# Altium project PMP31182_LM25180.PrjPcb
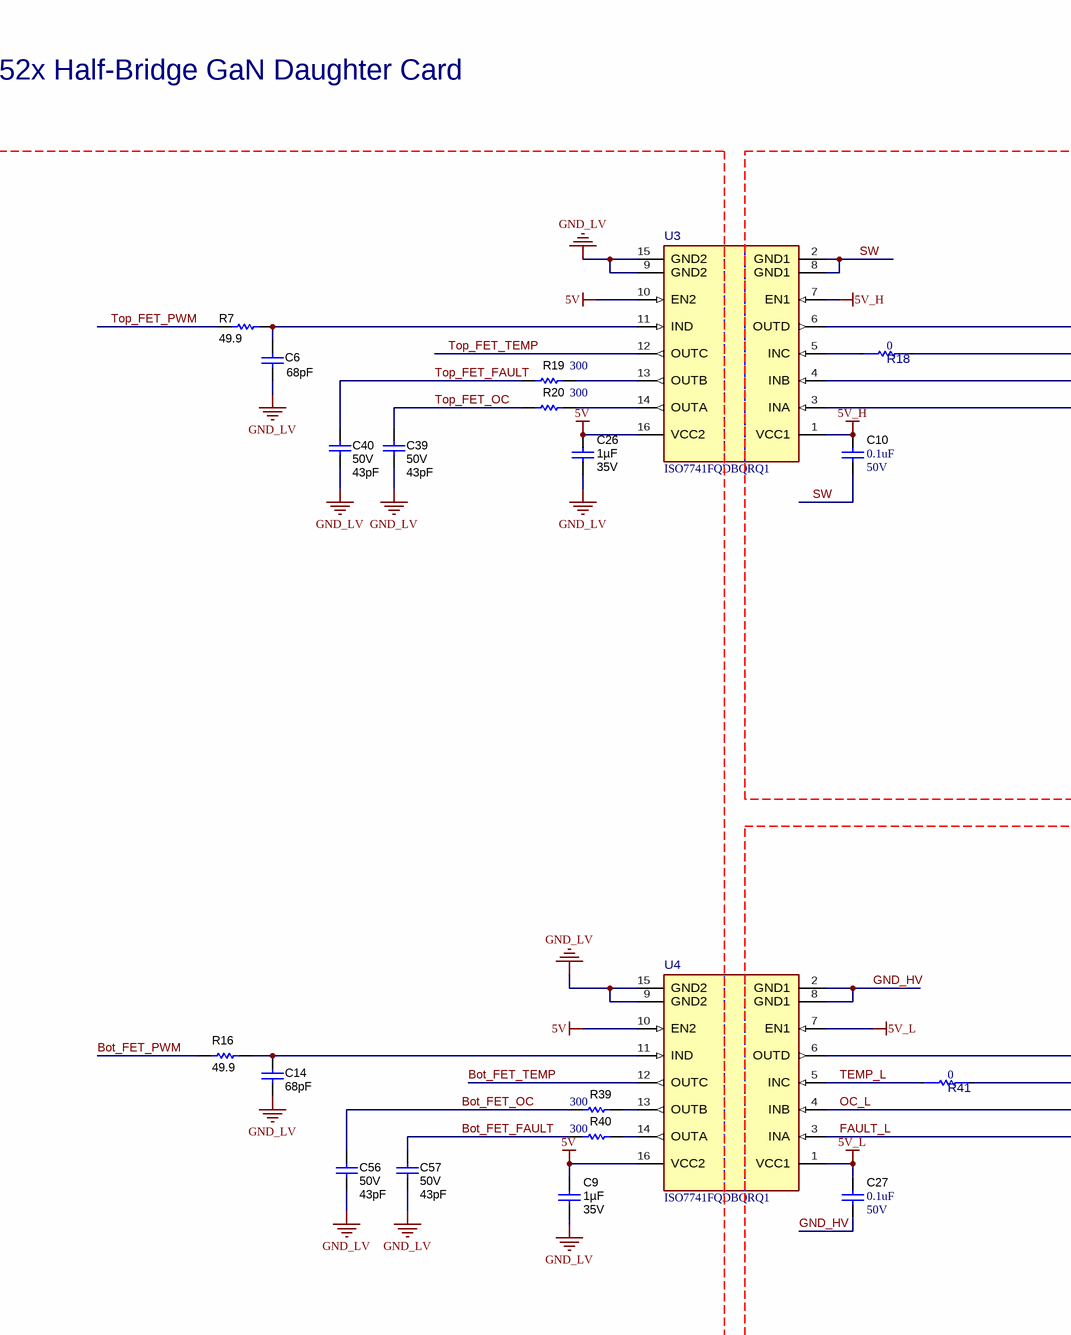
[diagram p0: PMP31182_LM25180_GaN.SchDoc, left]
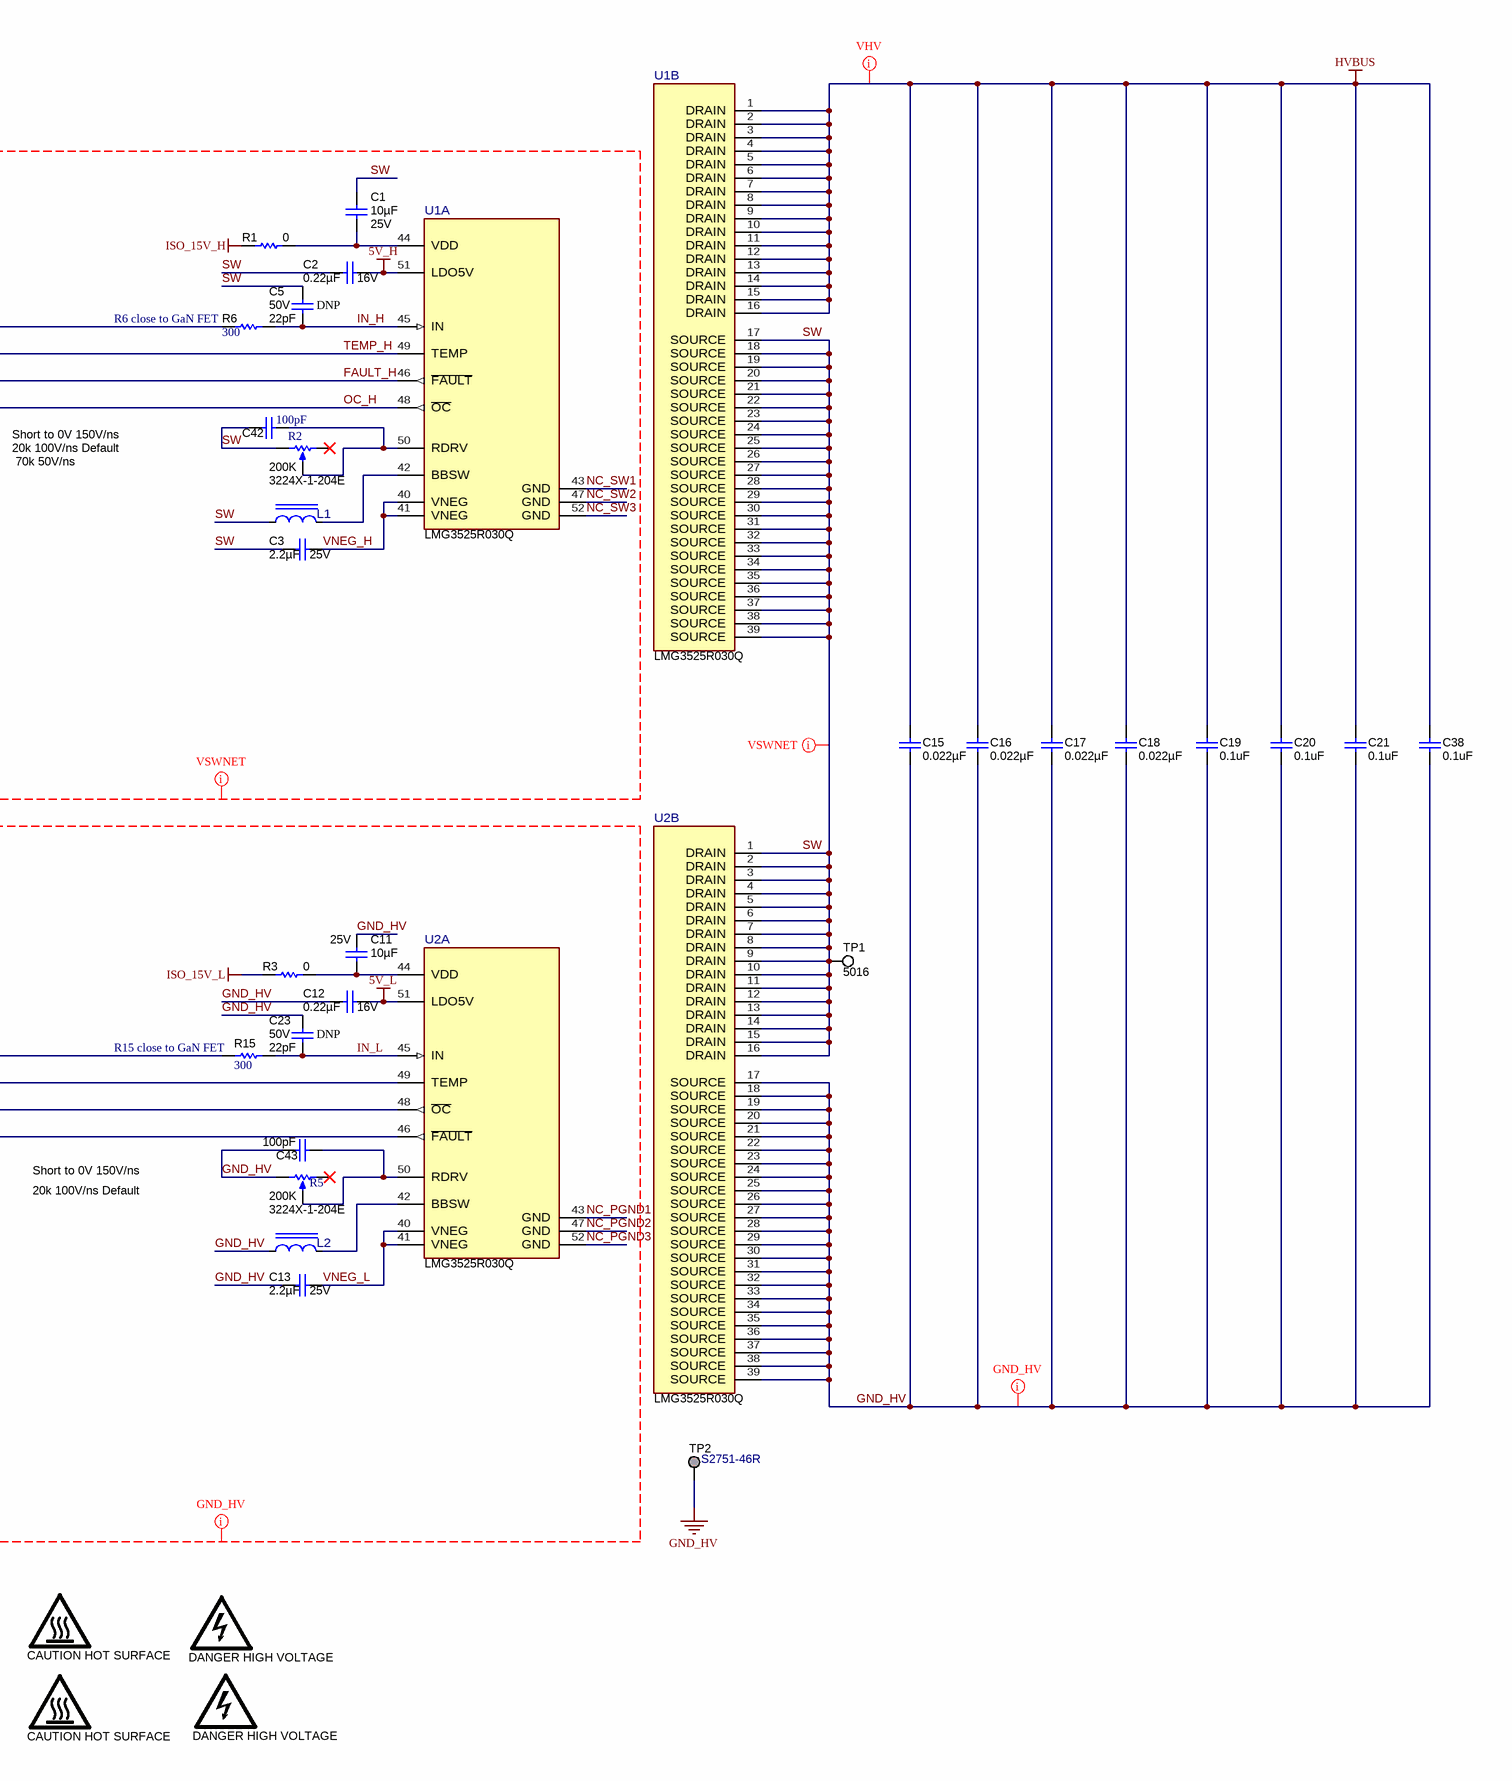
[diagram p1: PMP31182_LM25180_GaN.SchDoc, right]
TID: N/A; TechSupport: http://www.ti.com/support; SCH_Title: LM25180-Q1; PRJ_Title: Isolated Bias Power Supply; PRJ_Number: PMP31182; PRJ_Engineer: Prashant Kumar; PRJ_Customer: Public Release; PCB_Layout: Prashant Kumar; CopyrightYear: 2023
3 sheets, 164 parts. Net scope: global (net labels, ports and power ports of the same name join across sheets).
Board file: PMP31182_LM25180_PCB.PcbDoc
Sheets:
  PMP31182_LM25180_GaN.SchDoc
  PMP31182_LM25180_PWM.SchDoc
  PMP31182_LM25180_power_supply.SchDoc

## Sheet PMP31182_LM25180_GaN.SchDoc: LM25180-Q1
size A2; Date: Not shown in title block; ApprovedBy: Not shown in title block; CheckedBy: Not shown in title block; Author: Not shown in title block; CompanyName: Not shown in title block; Engineer: Not shown in title block; Organization: Not shown in title block; Address1: Not shown in title block; Address2: Not shown in title block; Address3: Not shown in title block; Address4: Not shown in title block; DocumentNumber: 2; Revision: Use project parameter SCH_Rev; SheetNumber: 2; SheetTotal: 3; PageSetup: Record=PageOptions¦CenterHorizontal=True¦CenterVertical=True¦PrintScale=1.00¦XCorrection=1.00¦YCorrection=1.00¦PrintKind=0¦BorderSize=5000000¦LeftOffset=0¦BottomOffset=0¦Orientation=2¦PaperLength=1000¦PaperWidth=1000¦Scale=100¦PaperSource=15¦PrintQuality=600¦MediaType=1¦DitherType=10¦PaperKind=Letter¦PrintScaleMode=1

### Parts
(Parts that share a designator on the sheet are numbered #1, #2 ... from top to bottom, then left to right.)
C1  VDC_V: 25V  ValueDisplayed: 10µF  [1206_180]  (hidden comment: TMK316AB7106KLHT)
C2  VDC_V: 16V  ValueDisplayed: 0.22µF  [0402]  (hidden comment: GCM155R71C224KE02D)
C3  Cap_F: 2.2µF  VDC_V: 25V  [0805_HV]  (hidden comment: CGA4J3X7R1E225K125AB)
C5  VDC_V: 50V  ValueDisplayed: 22pF  [0402]  (hidden comment: GCM1555C1H220JA16D)
C6  ValueDisplayed: 68pF  [0402]  (hidden comment: C1005C0G1H680J050BA)
C9  VDC_V: 35V  ValueDisplayed: 1µF  [0402]  (hidden comment: GRT155R6YA105KE13D)
C10  VDC_V: 50V  ValueDisplayed: 0.1uF  [0402]  (hidden comment: GCM155R71H104KE02D)
C11  VDC_V: 25V  ValueDisplayed: 10µF  [1206_180]  (hidden comment: TMK316AB7106KLHT)
C12  VDC_V: 16V  ValueDisplayed: 0.22µF  [0402]  (hidden comment: GCM155R71C224KE02D)
C13  Cap_F: 2.2µF  VDC_V: 25V  [0805_HV]  (hidden comment: CGA4J3X7R1E225K125AB)
C14  ValueDisplayed: 68pF  [0402]  (hidden comment: C1005C0G1H680J050BA)
C15  ValueDisplayed: 0.022µF  [1206_190]  (hidden comment: C1206C223KDRACTU)
C16  ValueDisplayed: 0.022µF  [1206_190]  (hidden comment: C1206C223KDRACTU)
C17  ValueDisplayed: 0.022µF  [1206_190]  (hidden comment: C1206C223KDRACTU)
C18  ValueDisplayed: 0.022µF  [1206_190]  (hidden comment: C1206C223KDRACTU)
C19  ValueDisplayed: 0.1uF  [1812_254]  (hidden comment: C1812W104KDRACTU)
C20  ValueDisplayed: 0.1uF  [1812_254]  (hidden comment: C1812W104KDRACTU)
C21  ValueDisplayed: 0.1uF  [1812_254]  (hidden comment: C1812W104KDRACTU)
C23  VDC_V: 50V  ValueDisplayed: 22pF  [0402]  (hidden comment: GCM1555C1H220JA16D)
C26  VDC_V: 35V  ValueDisplayed: 1µF  [0402]  (hidden comment: GRT155R6YA105KE13D)
C27  VDC_V: 50V  ValueDisplayed: 0.1uF  [0402]  (hidden comment: GCM155R71H104KE02D)
C38  ValueDisplayed: 0.1uF  [1812_254]  (hidden comment: C1812W104KDRACTU)
C39  VDC_V: 50V  ValueDisplayed: 43pF  [0402]  (hidden comment: GCQ1555C1H430JB01D)
C40  VDC_V: 50V  ValueDisplayed: 43pF  [0402]  (hidden comment: GCQ1555C1H430JB01D)
C42  ValueDisplayed: 100pF  [0402]  (hidden comment: CGA2B2C0G1H101J050BA)
C43  ValueDisplayed: 100pF  [0402]  (hidden comment: CGA2B2C0G1H101J050BA)
C56  VDC_V: 50V  ValueDisplayed: 43pF  [0402]  (hidden comment: GCQ1555C1H430JB01D)
C57  VDC_V: 50V  ValueDisplayed: 43pF  [0402]  (hidden comment: GCQ1555C1H430JB01D)
L1  MPIA2510V2-4R7-R  [FP-MPIA2510V2-4R7-R_1008-MFG]  (value not drawn)
L2  MPIA2510V2-4R7-R  [FP-MPIA2510V2-4R7-R_1008-MFG]  (value not drawn)
LOGO?#1  CAUTION HOT SURFACE  [IEC_HotSurface_Small]  (no BOM)
LOGO?#2  DANGER HIGH VOLTAGE  [IEC_HighVoltage_Small]  (no BOM)
LOGO?#3  CAUTION HOT SURFACE  [IEC_HotSurface_Small]  (no BOM)
LOGO?#4  DANGER HIGH VOLTAGE  [IEC_HighVoltage_Small]  (no BOM)
R1  ValueDisplayed: 0  [0805_HV]  (hidden comment: CRCW08050000Z0EAHP)
R2  3224X-1-204E  value 200K  [TRIM_3224X]
R3  ValueDisplayed: 0  [0805_HV]  (hidden comment: CRCW08050000Z0EAHP)
R5  3224X-1-204E  value 200K  [TRIM_3224X]
R6  ValueDisplayed: 300  [0402]  (hidden comment: CRCW0402300RJNED)
R7  ValueDisplayed: 49.9  [0402]  (hidden comment: CRCW040249R9FKED)
R15  ValueDisplayed: 300  [0402]  (hidden comment: CRCW0402300RJNED)
R16  ValueDisplayed: 49.9  [0402]  (hidden comment: CRCW040249R9FKED)
R18  Res_ohm: 0  [FP-ERJ-3GEY0R00V_0603-MFG]  (hidden comment: ERJ-3GEY0R00V)
R19  ValueDisplayed: 300  [0402]  (hidden comment: CRCW0402300RJNED)
R20  ValueDisplayed: 300  [0402]  (hidden comment: CRCW0402300RJNED)
R39  ValueDisplayed: 300  [0402]  (hidden comment: CRCW0402300RJNED)
R40  ValueDisplayed: 300  [0402]  (hidden comment: CRCW0402300RJNED)
R41  Res_ohm: 0  [FP-ERJ-3GEY0R00V_0603-MFG]  (hidden comment: ERJ-3GEY0R00V)
TP1  5016  [Testpoint_Keystone_Compact]
TP2  S2751-46R  [Harwin_S2751-46R]
U1  LMG3525R030Q  [RQS0052A-MFG]  (parts A,B of 2)
U2  LMG3525R030Q  [RQS0052A-MFG]  (parts A,B of 2)
U3  ISO7741FQDBQRQ1  [DBQ0016A-MFG]
U4  ISO7741FQDBQRQ1  [DBQ0016A-MFG]

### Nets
5V: C9.1 C26.1 U3.10(EN2) U3.16(VCC2) U4.10(EN2) U4.16(VCC2)
5V_H: C2.1 C10.1 U1.51(LDO5V) U3.1(VCC1) U3.7(EN1)
5V_L: C12.1 C27.1 U2.51(LDO5V) U4.1(VCC1) U4.7(EN1)
GND_HV: C11.1 C12.2 C13.1 C15.2 C16.2 C17.2 C18.2 C19.2 C20.2 C21.2 C23.1 C27.2 C38.2 C43.1 L2.1 R5.1(CCW) TP2.1 U2.17(SOURCE) U2.18(SOURCE) U2.19(SOURCE) U2.20(SOURCE) U2.21(SOURCE) U2.22(SOURCE) U2.23(SOURCE) U2.24(SOURCE) U2.25(SOURCE) U2.26(SOURCE) U2.27(SOURCE) U2.28(SOURCE) U2.29(SOURCE) U2.30(SOURCE) U2.31(SOURCE) U2.32(SOURCE) U2.33(SOURCE) U2.34(SOURCE) U2.35(SOURCE) U2.36(SOURCE) U2.37(SOURCE) U2.38(SOURCE) U2.39(SOURCE) U4.2(GND1) U4.8(GND1)
GND_LV: C6.2 C9.2 C14.1 C26.2 C39.2 C40.2 C56.2 C57.2 U3.9(GND2) U3.15(GND2) U4.9(GND2) U4.15(GND2)
HVBUS: C15.1 C16.1 C17.1 C18.1 C19.1 C20.1 C21.1 C38.1 U1.1(DRAIN) U1.2(DRAIN) U1.3(DRAIN) U1.4(DRAIN) U1.5(DRAIN) U1.6(DRAIN) U1.7(DRAIN) U1.8(DRAIN) U1.9(DRAIN) U1.10(DRAIN) U1.11(DRAIN) U1.12(DRAIN) U1.13(DRAIN) U1.14(DRAIN) U1.15(DRAIN) U1.16(DRAIN)
ISO_15V_H: R1.1
ISO_15V_L: R3.1
Bot_FET_FAULT: C57.1 R40.2
Bot_FET_OC: C56.1 R39.2
Bot_FET_PWM: R16.1
Bot_FET_TEMP: U4.12(OUTC)
FAULT_H: U1.46(~{FAULT}) U3.4(INB)
FAULT_L: U2.46(~{FAULT}) U4.3(INA)
IN_H: C5.2 R6.2 U1.45(IN)
IN_L: C23.2 R15.2 U2.45(IN)
NC_PGND1: U2.43(GND)
NC_PGND2: U2.47(GND)
NC_PGND3: U2.52(GND)
NC_SW1: U1.43(GND)
NC_SW2: U1.47(GND)
NC_SW3: U1.52(GND)
OC_H: U1.48(~{OC}) U3.3(INA)
OC_L: U2.48(~{OC}) U4.4(INB)
SW: C1.2 C2.2 C3.1 C5.1 C10.2 C42.2 L1.1 R2.1(CCW) TP1.1 U1.17(SOURCE) U1.18(SOURCE) U1.19(SOURCE) U1.20(SOURCE) U1.21(SOURCE) U1.22(SOURCE) U1.23(SOURCE) U1.24(SOURCE) U1.25(SOURCE) U1.26(SOURCE) U1.27(SOURCE) U1.28(SOURCE) U1.29(SOURCE) U1.30(SOURCE) U1.31(SOURCE) U1.32(SOURCE) U1.33(SOURCE) U1.34(SOURCE) U1.35(SOURCE) U1.36(SOURCE) U1.37(SOURCE) U1.38(SOURCE) U1.39(SOURCE) U2.1(DRAIN) U2.2(DRAIN) U2.3(DRAIN) U2.4(DRAIN) U2.5(DRAIN) U2.6(DRAIN) U2.7(DRAIN) U2.8(DRAIN) U2.9(DRAIN) U2.10(DRAIN) U2.11(DRAIN) U2.12(DRAIN) U2.13(DRAIN) U2.14(DRAIN) U2.15(DRAIN) U2.16(DRAIN) U3.2(GND1) U3.8(GND1)
TEMP_H: R18.2 U1.49(TEMP)
TEMP_L: R41.1 U4.5(INC)
Top_FET_FAULT: C40.1 R19.2
Top_FET_OC: C39.1 R20.2
Top_FET_PWM: R7.1
Top_FET_TEMP: U3.12(OUTC)
VNEG_H: C3.2 U1.40(VNEG) U1.41(VNEG)
VNEG_L: C13.2 U2.40(VNEG) U2.41(VNEG)
NetC1_1: C1.1 R1.2 U1.44(VDD)
NetC6_1: C6.1 R7.2 U3.11(IND)
NetC11_2: C11.2 R3.2 U2.44(VDD)
NetC14_2: C14.2 R16.2 U4.11(IND)
NetC42_1: C42.1 R2.2(WIPER) U1.50(RDRV)
NetC43_2: C43.2 R5.2(WIPER) U2.50(RDRV)
NetL1_2: L1.2 U1.42(BBSW)
NetL2_2: L2.2 U2.42(BBSW)
NetR6_1: R6.1 U3.6(OUTD)
NetR15_1: R15.1 U4.6(OUTD)
NetR18_1: R18.1 U3.5(INC)
NetR19_1: R19.1 U3.13(OUTB)
NetR20_1: R20.1 U3.14(OUTA)
NetR39_1: R39.1 U4.13(OUTB)
NetR40_1: R40.1 U4.14(OUTA)
NetR41_2: R41.2 U2.49(TEMP)

Not connected (* = marked no-connect by the designer): R2 3(CW)*; R5 3(CW)*

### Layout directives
net class VSWNET: 5V_H, FAULT_H, IN_H, ISO_15V_H, NC_SW1, NC_SW2, NC_SW3, OC_H, SW, TEMP_H, VNEG_H
net class VHV: HVBUS
net class INGND: (no net found under the mark)
net class PGND: 5V_L, FAULT_L, GND_HV, IN_L, ISO_15V_L, NC_PGND1, NC_PGND2, NC_PGND3, OC_L, TEMP_L, VNEG_L

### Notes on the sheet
- LMG352x Half-Bridge GaN Daughter Card
- (near C5) DNP
- (near R6) R6 close to GaN FET
- Short to 0V 150V/ns
- 20k 100V/ns Default
- 70k 50V/ns
- (near R15) R15 close to GaN FET
- (near C23) DNP

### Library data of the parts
C1 C11 = CMP-0750154-1: CAP, CERM, 10 µF, 25 V,+/- 10%, X7R, AEC-Q200 Grade 1, 1206; Manufacturer: Taiyo Yuden; AEC Qualified: Y; SizeZ_mm: 1.8; TaMax_C: 125°C; TaMin_C: -55°C; Cap_Case: 1206; Polarized: N; AEC Grade: 1; SizeY_mm: 1.6; Value: 10uF; SizeX_mm: 3.2; SizeAreaWB_mm2: 10.92; AEC Category: Q200; U/M: EA; SizeArea_mm2: 5.12
C2 C12 = CMP-0078265-1: CAP, CERM, 0.22 µF, 16 V,+/- 10%, X7R, AEC-Q200 Grade 1, 0402; Manufacturer: MuRata; TaMin_C: -55°C; Polarized: N; SizeAreaWB_mm2: 3; U/M: EA; Value: 0.22uF; TaMax_C: 125°C; SizeZ_mm: 0.6; SizeX_mm: 1; SizeY_mm: 0.5; AEC Qualified: Y; Cap_F: 220nF; AEC Category: Q200
C3 C13 = CMP-0007975-2: CAP, CERM, 2.2 uF, 25 V, +/- 10%, X7R, AEC-Q200 Grade 1, 0805; Manufacturer: TDK; TaMin_C: -55°C; Polarized: N; SizeAreaWB_mm2: 6.75; Value1: Unknown; U/M: EA; Value: 2.2uF; TaMax_C: 125°C; SizeZ_mm: 1.45; SizeX_mm: 2; SizeY_mm: 1.25; Cap_Case: 0805; SizeArea_mm2: 2.5; AEC Qualified: Y; AEC Grade: 1; AEC Category: Q200
C5 C23 = CMP-0006348-2: CAP, CERM, 22 pF, 50 V, +/- 5%, C0G/NP0, AEC-Q200 Grade 1, 0402; Manufacturer: MuRata; TaMin_C: -55°C; Polarized: N; SizeAreaWB_mm2: 3; Value1: Unknown; U/M: EA; Value: 22pF; TaMax_C: 125°C; SizeZ_mm: 0.6; SizeX_mm: 1; SizeY_mm: 0.5; AEC Qualified: Y; AEC Category: Q200
C6 C14 = CMP-0006251-2: CAP, CERM, 68 pF, 50 V, +/- 5%, C0G/NP0, 0402; Manufacturer: TDK; Alternate Manufacturer: Murata; Alternate PartNumber: GRM1555C1H680JA01D; TaMin_C: -55°C; Polarized: N; SizeAreaWB_mm2: 3; Value1: Unknown; U/M: EA; Value: 68pF; TaMax_C: 125°C; SizeZ_mm: 0.6; SizeX_mm: 1; SizeY_mm: 0.5; Value2: 50V; AEC Category: Q200
C9 C26 = CMP-0750099-1: CAP, CERM, 1 µF, 35 V,+/- 10%, X5R, AEC-Q200 Grade 3, 0402; Manufacturer: MuRata; AEC Grade: 3; AEC Category: Q200; Value: 1uF; SizeArea_mm2: 0.5; SizeZ_mm: 0.6; AEC Qualified: Y; TaMin_C: -55°C; SizeX_mm: 1; U/M: EA; Polarized: N; TaMax_C: 85°C
C10 C27 = CMP-0006356-2: CAP, CERM, 0.1 uF, 50 V, +/- 10%, X7R, AEC-Q200 Grade 1, 0402; Manufacturer: MuRata; TaMin_C: -55°C; Polarized: N; SizeAreaWB_mm2: 3; Value1: Unknown; U/M: EA; Value: 0.1uF; TaMax_C: 125°C; SizeZ_mm: 0.6; SizeX_mm: 1; SizeY_mm: 0.5; AEC Qualified: Y; Cap_F: 100nF; AEC Category: Q200
C15-C18 = CMP-0084048-1: CAP, CERM, 0.022 µF, 1000 V,+/- 10%, X7R, AEC-Q200 Grade 1, 1206; Manufacturer: Kemet; Polarized: N; CompType: Capacitor; Value: 0.022uF; U/M: EA; Cap_F: 22nF; VDC_V: 1kV; Value2: 1000V; TaMin_C: -55°C; TaMax_C: 125°C; Cap_Case: 1206; SizeArea_mm2: 5.12; SizeAreaWB_mm2: 10.92; SizeX_mm: 3.2; SizeY_mm: 1.6; SizeZ_mm: 1.9; AEC Category: Q200; AEC Qualified: Y; AEC Grade: 1
C19-C21 C38 = CMP-0009326-2: CAP, CERM, 0.1 uF, 1000 V, +/- 10%, X7R, 1812; Manufacturer: Kemet; Polarized: N; Value: 0.1uF; U/M: EA; Cap_F: 100nF; Value1: Unknown; VDC_V: 1kV; Value2: 1000V; TaMin_C: -55°C; TaMax_C: 125°C; Cap_Case: 1812; AEC Category: Q200; SizeArea_mm2: 14.4; SizeAreaWB_mm2: 23.1; SizeX_mm: 4.5; SizeY_mm: 3.2; SizeZ_mm: 2.54
C39 C40 C56 C57 = CMP-0860835-1: CAP, CERM, 43 pF, 50 V,+/- 5%, C0G/NP0, AEC-Q200 Grade 1, 0402; Manufacturer: MuRata; SizeY_mm: 0.5; SizeZ_mm: 0.6; AEC Qualified: Y; AEC Grade: 1; AEC Category: Q200; U/M: EA; Value: 43pF; Polarized: N; TaMin_C: -55°C; SizeAreaWB_mm2: 3; TaMax_C: 125°C
C42 = CMP-0006308-2: CAP, CERM, 100 pF, 50 V, +/- 5%, C0G/NP0, AEC-Q200 Grade 1, 0402; Manufacturer: TDK; TaMin_C: -55°C; Polarized: N; SizeAreaWB_mm2: 3; Value1: Unknown; U/M: EA; Value: 100pF; TaMax_C: 125°C; SizeZ_mm: 0.6; SizeX_mm: 1; SizeY_mm: 0.5; Value2: 50V; AEC Qualified: Y; AEC Category: Q200
C43 = CMP-0006308-1: CAP, CERM, 100 pF, 50 V, +/- 5%, C0G/NP0, AEC-Q200 Grade 1, 0402; Manufacturer: TDK; TaMin_C: -55°C; Polarized: N; SizeAreaWB_mm2: 3; Value1: Unknown; U/M: EA; Value: 100pF; TaMax_C: 125°C; SizeZ_mm: 0.6; SizeX_mm: 1; SizeY_mm: 0.5; Value2: 50V; AEC Qualified: Y; AEC Category: Q200
L1 L2 = CMP-0090507-1: 4.7µH Shielded Molded Inductor 1.22A 262mOhm Max 1008 (2520 Metric); Manufacturer: Eaton; Material: Metal Composite; Value: 4.7uH; Test Frequency: 1MHz; Isat: 1.8A; DCR_ohm: 0.262; AEC Grade: Grade 1; Tolerance_%: 20%; AEC Qualified: Yes; Self Resonant Frequency: 25MHz; SizeZ_mm: 1.05mm; Shrouded: true
LOGO?#1 LOGO?#3 = CMP-0074837-1: IEC 61010-1 Hot Surface Warning; SymbolCreator: a0412235; Lib Reference: IEC_HotSurface
LOGO?#2 LOGO?#4 = CMP-0074835-1: IEC 61010-1 High Voltage Warning; SymbolCreator: a0412235; Lib Reference: IEC_HighVoltage
R1 R3 = CMP-0020443-3: RES, 0, 5%, 0.333 W, AEC-Q200 Grade 0, 0805; Manufacturer: Vishay-Dale; Power_W: 333mW; TempCo: 200 ppm/C; Value_Code: 0000; Value: 0; EIA_Code: E24; SizeX_mm: 2; SizeY_mm: 1.25; SizeZ_mm: 1.45; Value2: 0.333W; SizeArea_mm2: 2.5; AEC Qualified: Y; AEC Category: Q200; VDC_V: 150V
R2 R5 = CMP-0002064-2: Trimmer, 200 K, 0.25 W, SMD; Manufacturer: Bourns
R6 R15 R19 R20 R39 R40 = CMP-0026902-3: RES, 300, 5%, 0.063 W, AEC-Q200 Grade 0, 0402; Manufacturer: Vishay-Dale; Power_W: 63mW; TempCo: 200 ppm/C; Value_Code: 300R; Value: 300; EIA_Code: E24; SizeX_mm: 1; SizeY_mm: 0.5; SizeZ_mm: 0.6; Value2: 0.063W; AEC Qualified: Y; VDC_V: 50V; AEC Category: Q200; AEC Grade: 0
R7 R16 = CMP-0026404-2: RES, 49.9, 1%, 0.063 W, AEC-Q200 Grade 0, 0402; Manufacturer: Vishay-Dale; Power_W: 63mW; TempCo: 100 ppm/C; Value_Code: 49R9; Value: 49.9; EIA_Code: E96; SizeX_mm: 1; SizeY_mm: 0.5; SizeZ_mm: 0.6; Value2: 0.063W; AEC Qualified: Y; VDC_V: 50V; AEC Category: Q200; AEC Grade: 0
R18 R41 = CMP-0089143-1: 0 Ohms Jumper 0.1W, 1/10W Chip Resistor 0603 (1608 Metric) Automotive AEC-Q200 Thick Film; Manufacturer: Panasonic; SizeZ_mm: 0.55mm; AEC Grade: Grade 0; VDC_V: 75V; TempCo: -100/+600ppm/°C; AEC Qualified: Yes; Power_W: 100mW; Tolerance_%: 5%
TP1 = CMP-0055153-1: Test Point, Compact, SMT; Manufacturer: Keystone; CNHeader: FALSE; Green_Lifecycle: Active; Green_REACh: Passed; CT: TRUE
TP2 = CMP-0003968-1: Test Point, SMT; Manufacturer: Harwin
U1 U2 = CMP-0089968-1: 650-V 30-mΩ GaN FET with Integrated Driver and Protection; Manufacturer: Texas Instruments; Output Voltage: 520V; Nominal Supply Current: 540uA; Min Supply Voltage: 7.5V; Standoff Height: 0mm; AEC Grade: Grade 1; Max Supply Voltage: 18V; Number Of Outputs: 1; AEC Qualified: Yes; TJmax_C: +125°C; SizeZ_mm: 1mm
U3 U4 = CMP-0090469-1: General Purpose Digital Isolator 2500Vrms 4 Channel 100Mbps 85kV/µs CMTI 16-SSOP (0.154", 3.90mm Width); Manufacturer: Texas Instruments; TaMin_C: -40°C; TaMax_C: +125°C; TJmax_C: +150°C; AEC Grade: Grade 1; Min Supply Voltage: 2.25V; AEC Qualified: Yes; Max Supply Voltage: 5.5V; Standoff Height: 0.11mm; Nominal Supply Current: 1.5-18mA; SizeZ_mm: 1.75mm

## Sheet PMP31182_LM25180_PWM.SchDoc: LM25180-Q1
size A3
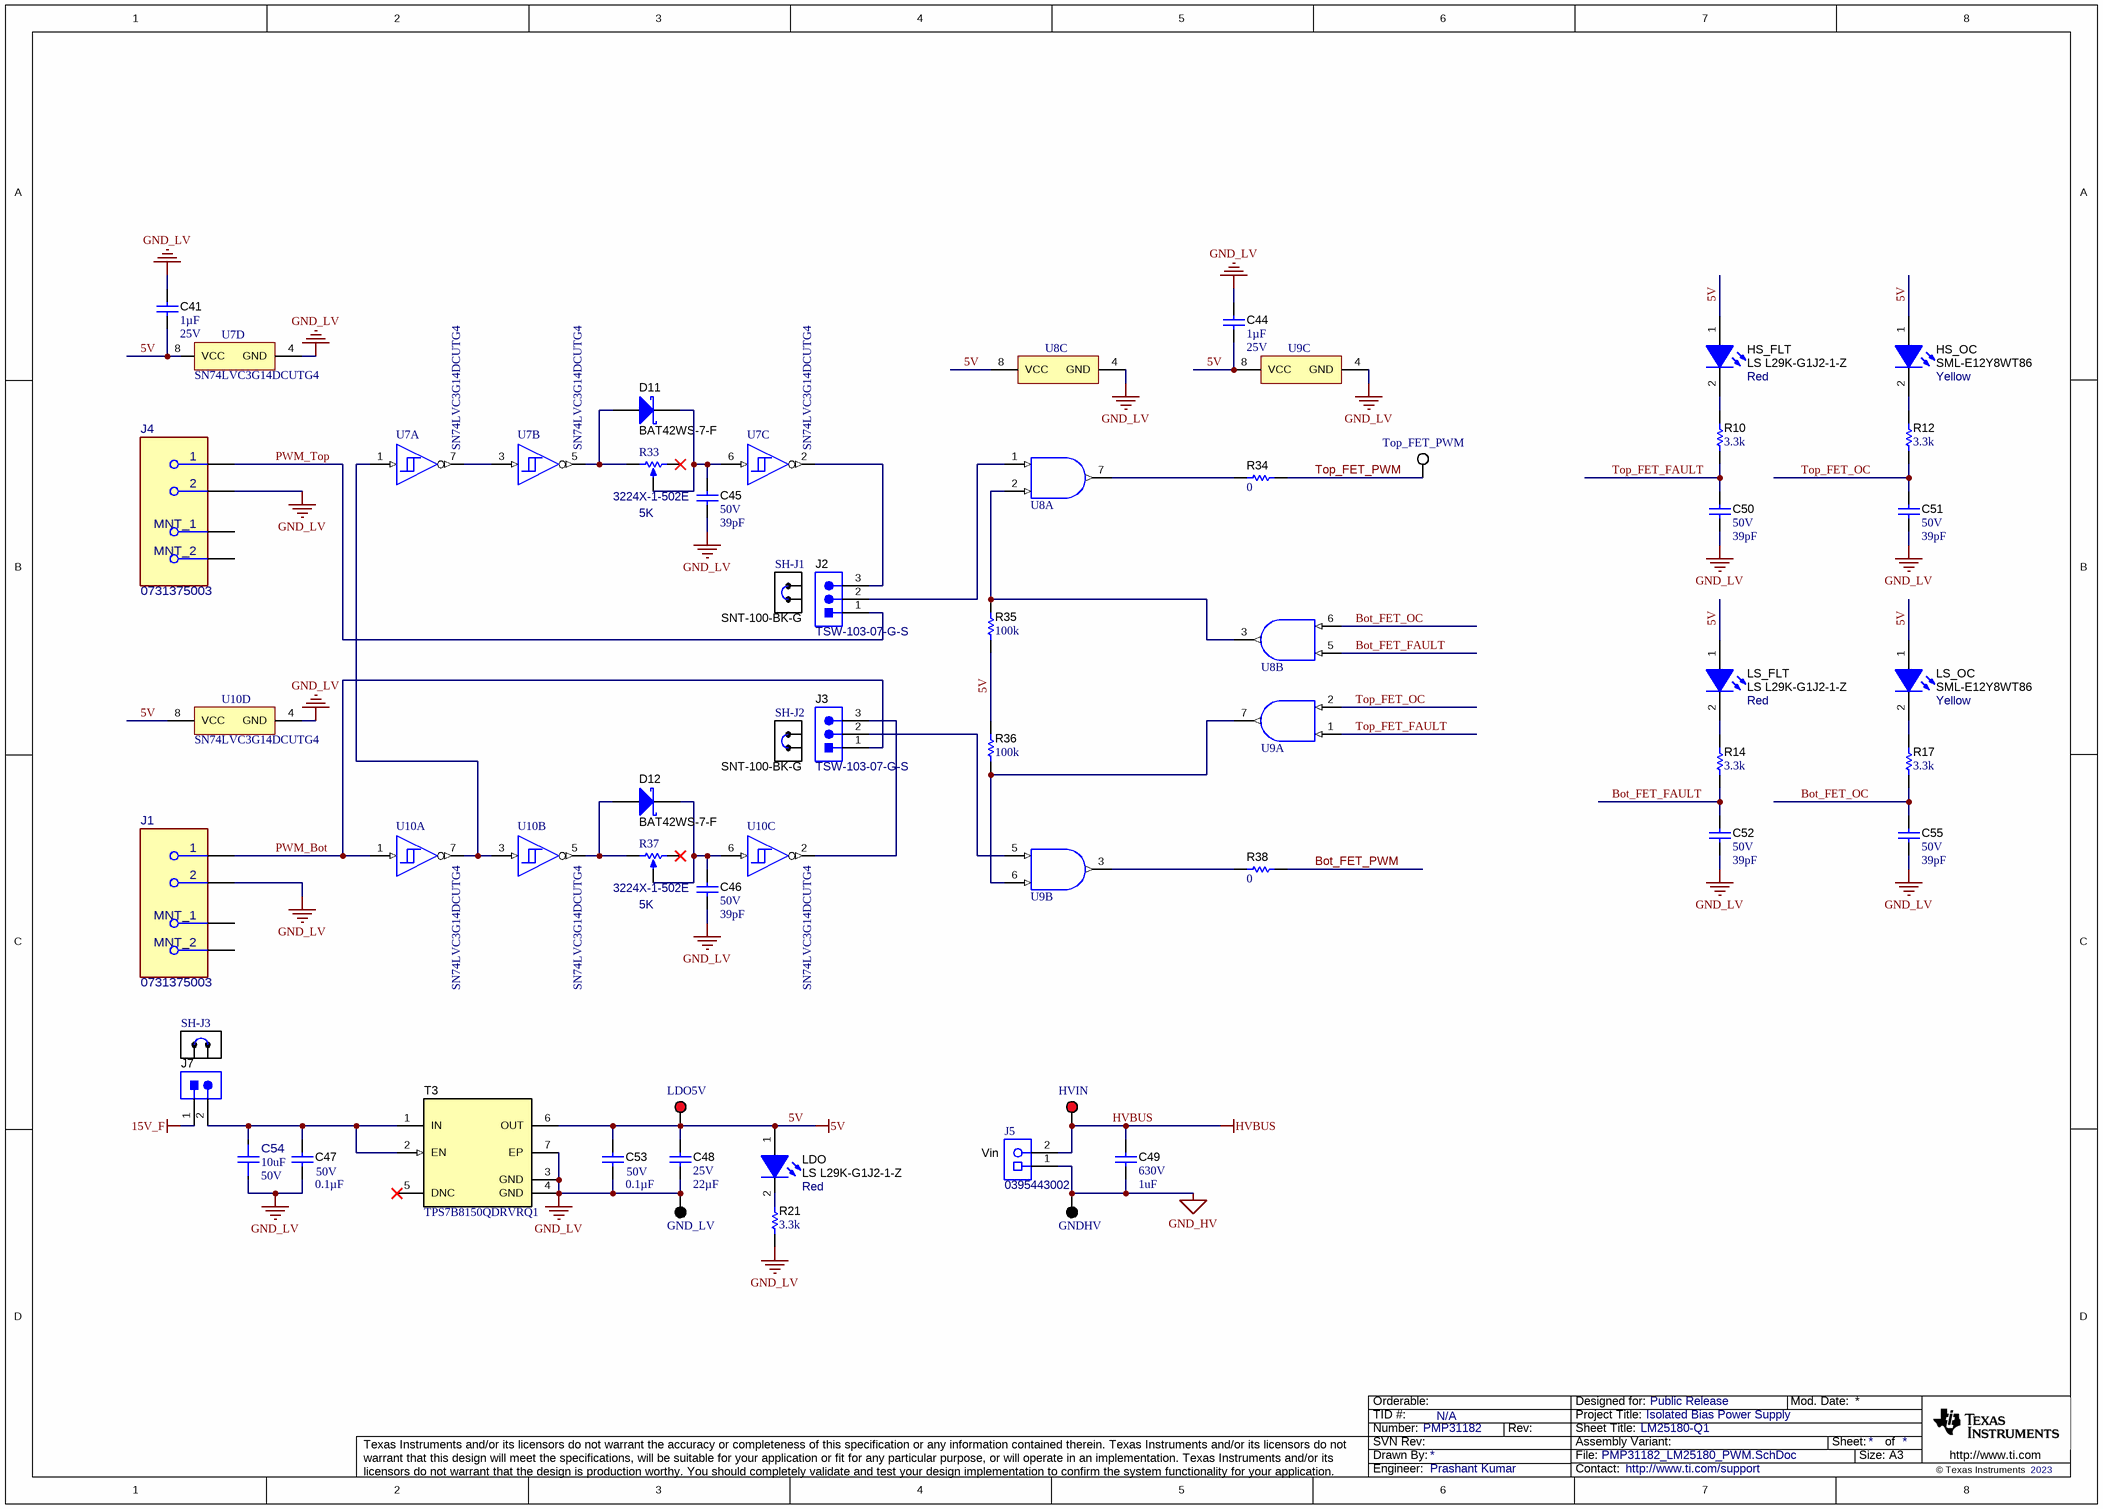
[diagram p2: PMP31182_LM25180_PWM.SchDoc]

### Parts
C41  Cap_F: 1µF  VDC_V: 25V  [0603]  (hidden comment: CGA3E1X7R1E105K080AD)
C44  Cap_F: 1µF  VDC_V: 25V  [0603]  (hidden comment: CGA3E1X7R1E105K080AD)
C45  VDC_V: 50V  ValueDisplayed: 39pF  [0603]  (hidden comment: GRM1885C1H390JA01D)
C46  VDC_V: 50V  ValueDisplayed: 39pF  [0603]  (hidden comment: GRM1885C1H390JA01D)
C47  VDC_V: 50V  ValueDisplayed: 0.1µF  [0603]  (hidden comment: CGA3E3X8R1H104K080AE)
C48  VDC_V: 25V  ValueDisplayed: 22µF  [1210_270]  (hidden comment: GRT32ER61E226KE13L)
C49  VDC_V: 630V  ValueDisplayed: 1uF  [2220_450]  (hidden comment: 2220Y6300105KETWS2)
C50  VDC_V: 50V  ValueDisplayed: 39pF  [0603]  (hidden comment: GRM1885C1H390JA01D)
C51  VDC_V: 50V  ValueDisplayed: 39pF  [0603]  (hidden comment: GRM1885C1H390JA01D)
C52  VDC_V: 50V  ValueDisplayed: 39pF  [0603]  (hidden comment: GRM1885C1H390JA01D)
C53  VDC_V: 50V  ValueDisplayed: 0.1µF  [0603]  (hidden comment: CGA3E3X8R1H104K080AE)
C54  ValueDisplayed: 10uF  VDC_V: 50V  [FP-UMK325AB7106KMHP_1210-MFG]  (hidden comment: UMK325AB7106KMHP)
C55  VDC_V: 50V  ValueDisplayed: 39pF  [0603]  (hidden comment: GRM1885C1H390JA01D)
D11  BAT42WS-7-F  [SOD-323]
D12  BAT42WS-7-F  [SOD-323]
GND_LV  5006  [Keystone5006]  (value not drawn)
GNDHV  5006  [Keystone5006]  (value not drawn)
HS_FLT  LS L29K-G1J2-1-Z  value Red  [LS L29K_Red]
HS_OC  SML-E12Y8WT86  value Yellow  [SML-E1_Yellow]
HVIN  5005  [Keystone5005]  (value not drawn)
J1  0731375003  [FP-0731375003_CONN_BNC_RCPT-MFG]
J2  TSW-103-07-G-S  [TSW-103-07-G-S]
J3  TSW-103-07-G-S  [TSW-103-07-G-S]
J4  0731375003  [FP-0731375003_CONN_BNC_RCPT-MFG]
J5  0395443002  [Molex_0395443002]
J7  TSW-102-07-G-S  [TSW-102-07-G-S]  (value not drawn)
LDO  LS L29K-G1J2-1-Z  value Red  [LS L29K_Red]
LDO5V  5005  [Keystone5005]  (value not drawn)
LS_FLT  LS L29K-G1J2-1-Z  value Red  [LS L29K_Red]
LS_OC  SML-E12Y8WT86  value Yellow  [SML-E1_Yellow]
R10  ValueDisplayed: 3.3k  [0603]  (hidden comment: CRCW06033K30JNEA)
R12  ValueDisplayed: 3.3k  [0603]  (hidden comment: CRCW06033K30JNEA)
R14  ValueDisplayed: 3.3k  [0603]  (hidden comment: CRCW06033K30JNEA)
R17  ValueDisplayed: 3.3k  [0603]  (hidden comment: CRCW06033K30JNEA)
R21  ValueDisplayed: 3.3k  [0603]  (hidden comment: CRCW06033K30JNEA)
R33  3224X-1-502E  value 5K  [TRIM_3224X]
R34  ValueDisplayed: 0  [0603_HV]  (hidden comment: CRCW06030000Z0EA)
R35  ValueDisplayed: 100k  [0603]  (hidden comment: CRCW0603100KJNEAC)
R36  ValueDisplayed: 100k  [0603]  (hidden comment: CRCW0603100KJNEAC)
R37  3224X-1-502E  value 5K  [TRIM_3224X]
R38  ValueDisplayed: 0  [0603_HV]  (hidden comment: CRCW06030000Z0EA)
SH-J1  SNT-100-BK-G  [SNT-100-BK-G]
SH-J2  SNT-100-BK-G  [SNT-100-BK-G]
SH-J3  SNT-100-BK-G  [SNT-100-BK-G]  (value not drawn)
T3  TPS7B8150QDRVRQ1  [DRV0006A]
Top_FET_PWM  5007  [Keystone5007]  (value not drawn)
U7  SN74LVC3G14DCUTG4  [DCU0008A_N]  (parts A,B,C,D of 4)
U8  SN74LVC2G08IDCTRQ1  [DCT0008A_N]  (value not drawn)  (parts A,B,C of 3)
U9  SN74LVC2G08IDCTRQ1  [DCT0008A_N]  (value not drawn)  (parts A,B,C of 3)
U10  SN74LVC3G14DCUTG4  [DCU0008A_N]  (parts A,B,C,D of 4)

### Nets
5V: C41.2 C44.2 C48.1 C53.1 HS_FLT.1(A) HS_OC.1(A) LDO.1(A) LDO5V.1 LS_FLT.1(A) LS_OC.1(A) R35.1 R36.2 T3.6(OUT) U7.8(VCC) U8.8(VCC) U9.8(VCC) U10.8(VCC)
15V_F: J7.1
GND_HV: C49.2 GNDHV.1 J5.1
GND_LV: C41.1 C44.1 C45.2 C46.2 C47.2 C48.2 C50.2 C51.2 C52.2 C53.2 C54.1 C55.2 GND_LV.1 J1.2 J4.2 R21.1 T3.3(GND) T3.4(GND) T3.7(EP) U7.4(GND) U8.4(GND) U9.4(GND) U10.4(GND)
HVBUS: C49.1 HVIN.1 J5.2
Bot_FET_FAULT: C52.1 R14.1 U8.5(2A)
Bot_FET_OC: C55.1 R17.1 U8.6(2B)
Bot_FET_PWM: R38.2
PWM_Bot: J1.1 J3.1 U10.1(1A)
PWM_Top: J2.1 J4.1
Top_FET_FAULT: C50.1 R10.1 U9.1(1A)
Top_FET_OC: C51.1 R12.1 U9.2(1B)
Top_FET_PWM: R34.2 Top_FET_PWM.1
NetC45_1: C45.1 D11.1(K) R33.2(WIPER) U7.6(3A)
NetC46_1: C46.1 D12.1(K) R37.2(WIPER) U10.6(3A)
NetC47_1: C47.1 C54.2 J7.2 T3.1(IN) T3.2(EN)
NetD11_2: D11.2(A) R33.1(CCW) U7.5(2Y)
NetD12_2: D12.2(A) R37.1(CCW) U10.5(2Y)
NetHS_FLT_2: HS_FLT.2(K) R10.2
NetHS_OC_2: HS_OC.2(K) R12.2
NetJ2_2: J2.2 U8.1(1A)
NetJ2_3: J2.3 U7.2(3Y)
NetJ3_2: J3.2 U9.5(2A)
NetJ3_3: J3.3 U10.2(3Y)
NetLDO_2: LDO.2(K) R21.2
NetLS_FLT_2: LS_FLT.2(K) R14.2
NetLS_OC_2: LS_OC.2(K) R17.2
NetR34_1: R34.1 U8.7(1Y)
NetR35_2: R35.2 U8.2(1B) U8.3(2Y)
NetR36_1: R36.1 U9.6(2B) U9.7(1Y)
NetR38_1: R38.1 U9.3(2Y)
NetU7_1: U7.1(1A) U10.3(2A) U10.7(1Y)
NetU7_3: U7.3(2A) U7.7(1Y)

Not connected (* = marked no-connect by the designer): J1 3(MNT_1) 4(MNT_2); J4 3(MNT_1) 4(MNT_2); R33 3(CW)*; R37 3(CW)*; T3 5(DNC)*

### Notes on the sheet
- (near J5) Vin

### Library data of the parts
C41 C44 = CMP-0082523-1: CAP, CERM, 1 µF, 25 V,+/- 10%, X7R, AEC-Q200 Grade 1, 0603; Manufacturer: TDK; SizeAreaWB_mm2: 4.68; SizeArea_mm2: 1.28; AEC Qualified: Y; AEC Category: Q200; Value: 1uF; TaMax_C: 125°C; SizeZ_mm: 1; Polarized: N; TaMin_C: -55°C; SizeY_mm: 0.8; U/M: EA; SizeX_mm: 1.6
C45 C46 C50-C52 C55 = CMP-0007214-4: CAP, CERM, 39 pF, 50 V, +/- 5%, C0G/NP0, 0603; Manufacturer: MuRata; TaMin_C: -55°C; Polarized: N; SizeAreaWB_mm2: 4.68; Value1: Unknown; U/M: EA; Value: 39pF; TaMax_C: 125°C; SizeZ_mm: 1; SizeX_mm: 1.6; SizeY_mm: 0.8; SizeArea_mm2: 1.28; AEC Category: Q200
C47 C53 = CMP-0079911-1: CAP, CERM, 0.1 µF, 50 V,+/- 10%, X8R, AEC-Q200 Grade 0, 0603; Manufacturer: TDK; Cap_F: 100nF; SizeAreaWB_mm2: 4.68; SizeArea_mm2: 1.28; AEC Qualified: Y; AEC Category: Q200; Value: 0.1uF; TaMax_C: 150°C; SizeZ_mm: 1; AEC Grade: 0; Polarized: N; TaMin_C: -55°C; SizeY_mm: 0.8; U/M: EA; SizeX_mm: 1.6
C48 = CMP-0084059-1: CAP, CERM, 22 µF, 25 V,+/- 10%, X5R, AEC-Q200 Grade 3, 1210; Manufacturer: MuRata; SizeAreaWB_mm2: 14.7; SizeArea_mm2: 8; AEC Qualified: Y; AEC Category: Q200; Value: 22uF; TaMax_C: 85°C; SizeZ_mm: 2.7; AEC Grade: 3; Polarized: N; TaMin_C: -55°C; SizeY_mm: 2.5; U/M: EA; SizeX_mm: 3.2; Cap_Case: 1210
C49 = CMP-0064919-2: CAP, CERM, 1 uF, 630 V,+/- 10%, X7R, AEC-Q200 Grade 1, 2220; Manufacturer: Knowles Capacitors; PartNumber: 2220Y6300105KXTWS2; TaMin_C: -55°C; Polarized: N; SizeAreaWB_mm2: 53.9; Value1: Unknown; U/M: EA; Value: 1uF; TaMax_C: 125°C; SizeZ_mm: 4.5; SizeX_mm: 5.7; SizeY_mm: 5; Cap_Case: 2220; SizeArea_mm2: 28.5; AEC Qualified: Y; Cap_F: 1µF; AEC Grade: 1; AEC Category: Q200
C54 = CMP-0089980-1: 10µF ±10% 50V Ceramic Capacitor X7R 1210 (3225 Metric); Manufacturer: Taiyo Yuden; SizeZ_mm: 2.8mm; AEC Qualified: Yes; AEC Grade: Grade 1; TempCo: 15%
D11 D12 = CMP-0028447-2: Diode, Schottky, 30 V, 0.2 A, SOD-323; Manufacturer: Diodes Inc.; SizeZ_mm: 1; AEC Category: Q101; Green_REACh: Incomplete; Green_Lifecycle: Not Set; Vr_V: 30V; Vf_V: 1V; Io_A: 200mA; SizeY_mm: 1.35; Value1: 0.2A; Value: 30V; SizeArea_mm2: 3.645; SizeX_mm: 2.7; SizeAreaWB_mm2: 8.695
GND_LV GNDHV = CMP-0055143-1: Test Point, Compact, Black, TH; Manufacturer: Keystone; CNHeader: FALSE; Green_Lifecycle: Active; Green_REACh: Passed; ContactFinish: Silver; CT: TRUE
HS_FLT LDO LS_FLT = CMP-0002902-2: LED, Red, SMD; Manufacturer: OSRAM; Io_A: 20mA; Vr_V: 12V; Tjmax_C: 110°C; Value1: W; Angle: 160; Vf_V: 1.8V
HS_OC LS_OC = CMP-0002977-1: LED, Yellow, SMD; Manufacturer: Rohm; Io_A: 20mA; Power_TotalModule: 54mW; Vr_V: 5V; Tjmax_C: 85°C; Value1: 0.054W; U/M: EA; Ir_A: 10µA; Vf_V: 2.2V; LuminousIntensity_IV: 63
HVIN LDO5V = CMP-0055142-1: Test Point, Compact, Red, TH; Manufacturer: Keystone; CNHeader: FALSE; Green_Lifecycle: Active; Green_REACh: Passed; ContactFinish: Silver; CT: TRUE
J1 J4 = CMP-0095823-1: Connector BNC Female 0Hz To 2GHz 50 Ohm Solder Right Angle Through Hole Gold Tray; Manufacturer: Molex; Voltage_V: 500V; Impedance: 50Ω; Standoff Height: 0.57mm; Is Female: yes; ContactFinish: Gold,Tin,Nickel; Dielectric Material: Polypropylene; SizeZ_mm: 13.33mm; AEC Qualified: No
J2 J3 = CMP-0075407-2: Header, 100mil, 3x1, Gold, TH; Manufacturer: Samtec; Pitch_mm: 2.54; Cert_VDE: N; Gender: Male; Cert_CSA: Y; Voltage_V: 550V; Green_REACh: Passed; Current_A: 6.3A; Green_Lifecycle: Active; Row_Count: 1
J5 = CMP-0055342-2: Terminal Block, 5.08mm, 2x1, TH; Manufacturer: Molex; Current_A: 15A; Green_Lifecycle: Not Set; Gender: Female; Green_REACh: Incomplete; Voltage_V: 300V; Row_Count: 1; Pitch_mm: 5.08
J7 = CMP-0075405-2: Header, 100mil, 2x1, Gold, TH; Manufacturer: Samtec; Pitch_mm: 2.54; Cert_VDE: N; Gender: Male; Cert_CSA: Y; Voltage_V: 550V; Green_REACh: Passed; Current_A: 6.3A; Green_Lifecycle: Active; Row_Count: 1
R10 R12 R14 R17 R21 = CMP-0025797-4: RES, 3.3 k, 5%, 0.1 W, AEC-Q200 Grade 0, 0603; Manufacturer: Vishay-Dale; Power_W: 100mW; TempCo: 200 ppm/C; Value_Code: 3k30; Value: 3.3k; EIA_Code: E24; SizeX_mm: 1.6; SizeY_mm: 0.8; SizeZ_mm: 1; Value2: 0.1W; SizeArea_mm2: 1.28; AEC Qualified: Y; VDC_V: 75V; AEC Category: Q200; AEC Grade: 0
R33 R37 = CMP-0002062-2: Trimmer, 5 K, 0.25 W, SMD; Manufacturer: Bourns
R34 R38 = CMP-0025697-4: RES, 0, 5%, 0.1 W, AEC-Q200 Grade 0, 0603; Manufacturer: Vishay-Dale; Power_W: 100mW; TempCo: 200 ppm/C; Value_Code: 0000; Value: 0; EIA_Code: E24; SizeX_mm: 1.6; SizeY_mm: 0.8; SizeZ_mm: 1; Value2: 0.1W; SizeArea_mm2: 1.28; AEC Qualified: Y; VDC_V: 75V; AEC Category: Q200
R35 R36 = CMP-0082530-1: RES, 100 k, 5%, 0.1 W, 0603; Manufacturer: Vishay-Dale; Power_W: 100mW; TempCo: 200 ppm/C; SizeAreaWB_mm2: 4.68; Value: 100k; EIA_Code: E24; SizeX_mm: 1.6; SizeY_mm: 0.8; SizeZ_mm: 1; Value2: 0.1W; SizeArea_mm2: 1.28; AEC Qualified: N; VDC_V: 75V; AEC Category: Q200
SH-J1-SH-J3 = CMP-0003623-3: Shunt, 100mil, Gold plated, Black; Alternate PartNumber: 969102-0000-DA; Manufacturer: Samtec; Alternate Manufacturer: 3M; Value: 1x2
T3 = CMP-0086086-2: 150-mA High-Voltage Ultralow-IQ Low-Dropout Regulator, DRV0006A (WSON-6); Alternate Manufacturer: Texas Instruments; AEC Category: Q200; CompType: IC; SizeArea_mm2: 4; SizeY_mm: 2; SizeAreaWB_mm2: 9; AEC Qualified: Y; SizeZ_mm: 0.8
Top_FET_PWM = CMP-0055144-1: Test Point, Compact, White, TH; Manufacturer: Keystone; CNHeader: FALSE; Green_Lifecycle: Active; Green_REACh: Passed; ContactFinish: Silver; CT: TRUE
U7 U10 = CMP-0051969-2: Triple Schmitt-Trigger Inverter, DCU0008A (VSSOP-8); Manufacturer: Texas Instruments; Output Type: CMOS; Logic: Inverting; tpd @ Nom Voltage(Max)(ns): 9.2,5.7,5.4,4.3; Bits(#): 3; ICC @ Nom Voltage(Max)(mA): 0.01; Output Drive (IOL/IOH)(Max)(mA): 32/-32; F @ Nom Voltage(Max)(Mhz): 150; Voltage(Nom)(V): 1.8,2.5,3.3,5; Input Type: CMOS/TTL; Schmitt Trigger: Yes; VCC(Max)(V): 5.5; VCC(Min)(V): 1.65; Technology Family: LVC; Rating: Catalog; 3-State Output: No; AEC Category: Q200; AEC Qualified: N; CompType: IC; SizeAreaWB_mm2: 12.6; SizeArea_mm2: 6.4; SizeX_mm: 3.2; SizeY_mm: 2.0; SizeZ_mm: 0.9
U8 U9 = CMP-0051803-1: Automotive Catalog Dual 2-Input Positive-AND Gate, DCT0008A, LARGE T&R; Manufacturer: Texas Instruments; Generic Part Number: SN74LVC2G08-Q1; F @ Nom Voltage(Max)(Mhz): 150; ICC @ Nom Voltage(Max)(mA): 0.01; Input Type: CMOS/TTL; Output Type: CMOS; Logic: True; VCC(Max)(V): 5.5; Technology Family: LVC; Schmitt Trigger: No; Bits(#): 2; tpd @ Nom Voltage(Max)(ns): 9,5.1,4.7,3.8; VCC(Min)(V): 1.65; Voltage(Nom)(V): 1.8,2.5,3.3,5; Output Drive (IOL/IOH)(Max)(mA): 32/-32

## Sheet PMP31182_LM25180_power_supply.SchDoc: LM25180-Q1
size A3; Date: Not shown in title block; ApprovedBy: Not shown in title block; CheckedBy: Not shown in title block; Author: Not shown in title block; CompanyName: Not shown in title block; Engineer: Not shown in title block; Organization: Not shown in title block; Address1: Not shown in title block; Address2: Not shown in title block; Address3: Not shown in title block; Address4: Not shown in title block; DocumentNumber: 1; Revision: Use project parameter SCH_Rev; SheetNumber: 1; SheetTotal: 1; PageSetup: Record=PageOptions¦CenterHorizontal=True¦CenterVertical=True¦PrintScale=0.69¦XCorrection=1.00¦YCorrection=1.00¦PrintKind=0¦BorderSize=5000000¦LeftOffset=0¦BottomOffset=0¦Orientation=2¦PaperLength=1000¦PaperWidth=1000¦Scale=100¦PaperSource=15¦PrintQuality=600¦MediaType=1¦DitherType=10¦PaperKind=Letter¦PrintScaleMode=1
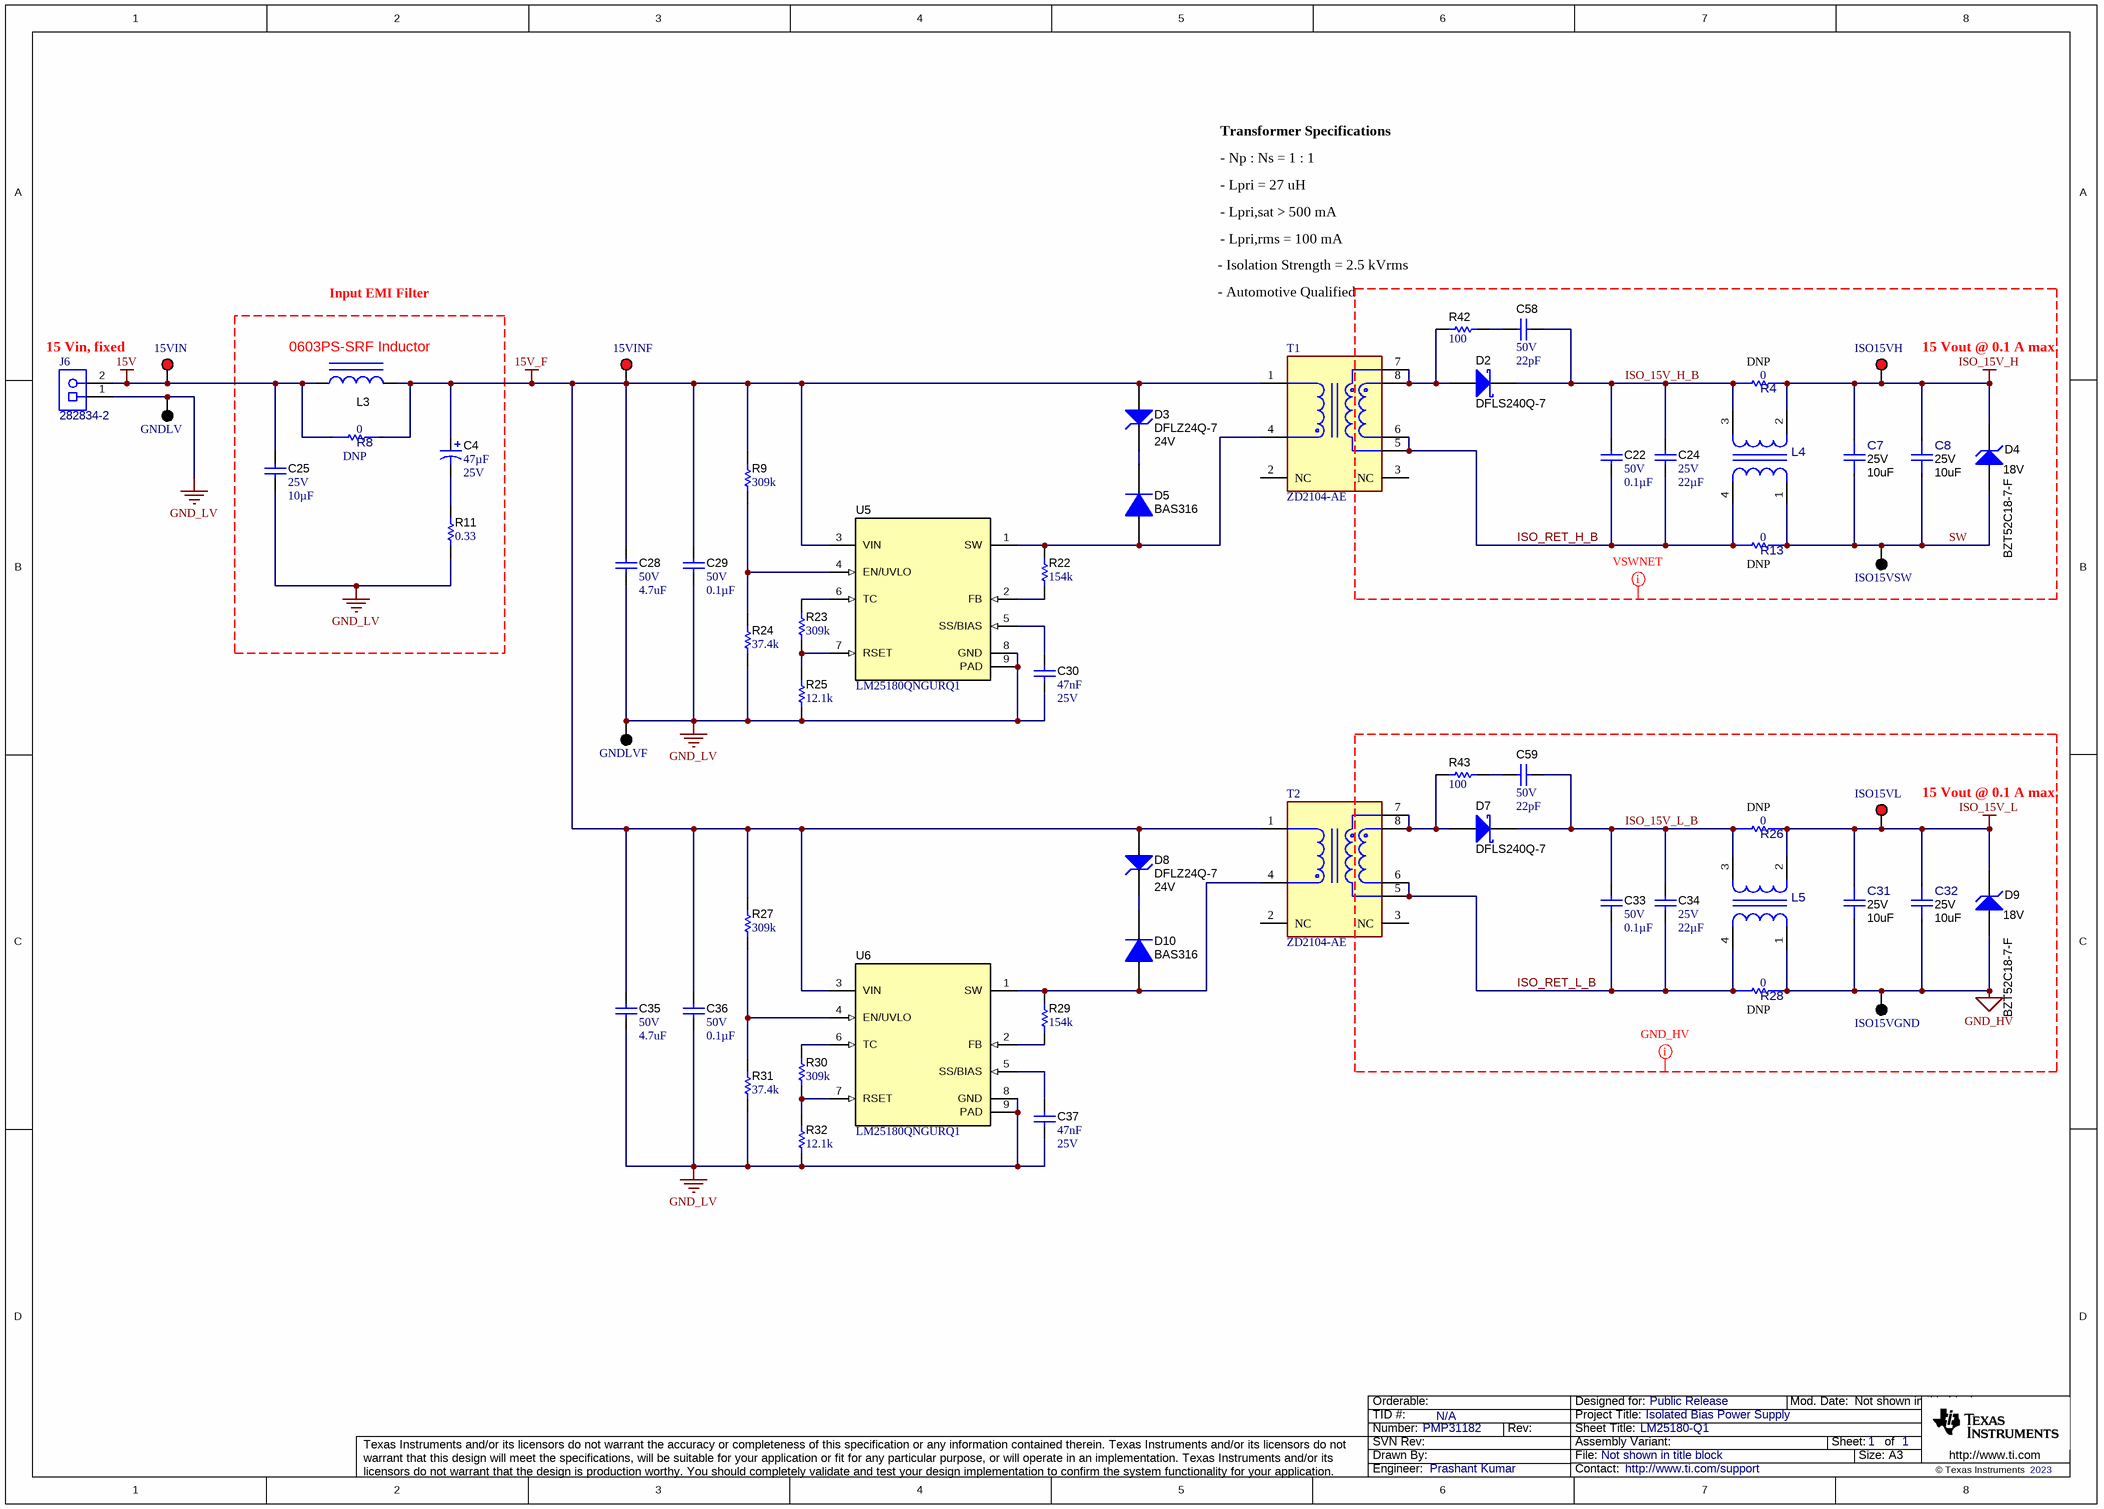
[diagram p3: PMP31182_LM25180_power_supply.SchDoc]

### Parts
15VIN  5005  [Keystone5005]  (value not drawn)
15VINF  5005  [Keystone5005]  (value not drawn)
C4  ValueDisplayed: 47µF  VDC_V: 25V  [HXB_F61]  (hidden comment: HHXC250ARA470MF61G)
C7  VDC_V: 25V  ValueDisplayed: 10uF  [FP-CGA4J1X7S1E106K125AC_0805-MFG]  (hidden comment: CGA4J1X7S1E106K125AC)
C8  VDC_V: 25V  ValueDisplayed: 10uF  [FP-CGA4J1X7S1E106K125AC_0805-MFG]  (hidden comment: CGA4J1X7S1E106K125AC)
C22  VDC_V: 50V  ValueDisplayed: 0.1µF  [0603]  (hidden comment: CGA3E3X8R1H104K080AE)
C24  VDC_V: 25V  ValueDisplayed: 22µF  [1210_270]  (hidden comment: TMK325B7226KMHP)
C25  VDC_V: 25V  ValueDisplayed: 10µF  [1206_180]  (hidden comment: C1206C106J3RACAUTO)
C28  VDC_V: 50V  ValueDisplayed: 4.7uF  [1210_280]  (hidden comment: CGA6P3X7R1H475M250AB)
C29  VDC_V: 50V  ValueDisplayed: 0.1µF  [0603]  (hidden comment: CGA3E3X8R1H104K080AE)
C30  Cap_F: 47nF  VDC_V: 25V  [0603]  (hidden comment: 06033C473JAT2A)
C31  VDC_V: 25V  ValueDisplayed: 10uF  [FP-CGA4J1X7S1E106K125AC_0805-MFG]  (hidden comment: CGA4J1X7S1E106K125AC)
C32  VDC_V: 25V  ValueDisplayed: 10uF  [FP-CGA4J1X7S1E106K125AC_0805-MFG]  (hidden comment: CGA4J1X7S1E106K125AC)
C33  VDC_V: 50V  ValueDisplayed: 0.1µF  [0603]  (hidden comment: CGA3E3X8R1H104K080AE)
C34  VDC_V: 25V  ValueDisplayed: 22µF  [1210_270]  (hidden comment: TMK325B7226KMHP)
C35  VDC_V: 50V  ValueDisplayed: 4.7uF  [1210_280]  (hidden comment: CGA6P3X7R1H475M250AB)
C36  VDC_V: 50V  ValueDisplayed: 0.1µF  [0603]  (hidden comment: CGA3E3X8R1H104K080AE)
C37  Cap_F: 47nF  VDC_V: 25V  [0603]  (hidden comment: 06033C473JAT2A)
C58  VDC_V: 50V  ValueDisplayed: 22pF  [0603]  (hidden comment: GRM1885C1H220JA01D)
C59  VDC_V: 50V  ValueDisplayed: 22pF  [0603]  (hidden comment: GRM1885C1H220JA01D)
D2  DFLS240Q-7  [PowerDI123]
D3  DFLZ24Q-7  value 24V  [PowerDI123]
D4  BZT52C18-7-F  value 18V  [SOD-123]
D5  BAS316  [SOD-323]
D7  DFLS240Q-7  [PowerDI123]
D8  DFLZ24Q-7  value 24V  [PowerDI123]
D9  BZT52C18-7-F  value 18V  [SOD-123]
D10  BAS316  [SOD-323]
GNDLV  5006  [Keystone5006]  (value not drawn)
GNDLVF  5006  [Keystone5006]  (value not drawn)
ISO15VGND  5006  [Keystone5006]  (value not drawn)
ISO15VH  5005  [Keystone5005]  (value not drawn)
ISO15VL  5005  [Keystone5005]  (value not drawn)
ISO15VSW  5006  [Keystone5006]  (value not drawn)
J6  282834-2  [TEC_282834-2]
L3  0603PS-SRF Inductor  [0603AF]
L4  ACM2012-900-2P-T001  [FP-ACM2012-900-2P-T001_SMD4-MFG]  (value not drawn)
L5  ACM2012-900-2P-T001  [FP-ACM2012-900-2P-T001_SMD4-MFG]  (value not drawn)
R4  Res_ohm: 0  [FP-ERJ-3GEY0R00V_0603-MFG]  (hidden comment: ERJ-3GEY0R00V)
R8  Res_ohm: 0  [FP-ERJ-3GEY0R00V_0603-MFG]  (hidden comment: ERJ-3GEY0R00V)
R9  ValueDisplayed: 309k  [0603]  (hidden comment: RT0603BRD07309KL)
R11  ValueDisplayed: 0.33  [0603]  (hidden comment: ERJ-3RQFR33V)
R13  Res_ohm: 0  [FP-ERJ-3GEY0R00V_0603-MFG]  (hidden comment: ERJ-3GEY0R00V)
R22  ValueDisplayed: 154k  [0603]  (hidden comment: RT0603DRE07154KL)
R23  ValueDisplayed: 309k  [0603]  (hidden comment: RT0603BRD07309KL)
R24  ValueDisplayed: 37.4k  [0603]  (hidden comment: RT0603BRD0737K4L)
R25  ValueDisplayed: 12.1k  [0603]  (hidden comment: RT0603BRD0712K1L)
R26  Res_ohm: 0  [FP-ERJ-3GEY0R00V_0603-MFG]  (hidden comment: ERJ-3GEY0R00V)
R27  ValueDisplayed: 309k  [0603]  (hidden comment: RT0603BRD07309KL)
R28  Res_ohm: 0  [FP-ERJ-3GEY0R00V_0603-MFG]  (hidden comment: ERJ-3GEY0R00V)
R29  ValueDisplayed: 154k  [0603]  (hidden comment: RT0603DRE07154KL)
R30  ValueDisplayed: 309k  [0603]  (hidden comment: RT0603BRD07309KL)
R31  ValueDisplayed: 37.4k  [0603]  (hidden comment: RT0603BRD0737K4L)
R32  ValueDisplayed: 12.1k  [0603]  (hidden comment: RT0603BRD0712K1L)
R42  ValueDisplayed: 100  [0603]  (hidden comment: RC0603FR-07100RL)
R43  ValueDisplayed: 100  [0603]  (hidden comment: RC0603FR-07100RL)
T1  ZD2104-AE  [FP-YA9035-ALD-MFG]
T2  ZD2104-AE  [FP-YA9035-ALD-MFG]
U5  LM25180QNGURQ1  [NGU0008C]
U6  LM25180QNGURQ1  [NGU0008C]

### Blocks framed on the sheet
Input EMI Filter: C4 C25 L3 R8 R11

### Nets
15V: 15VIN.1 C25.1 J6.2 L3.1 R8.1
15V_F: 15VINF.1 C4.1(+) C28.1 C29.1 C35.1 C36.1 D3.2(A) D8.2(A) L3.2 R8.2 R9.2 R27.2 T1.1 T2.1 U5.3(VIN) U6.3(VIN)
GND_HV: C31.2 C32.2 D9.2(A) ISO15VGND.1 L5.1 R28.2
GND_LV: C25.2 C28.2 C29.2 C30.2 C35.2 C36.2 C37.2 GNDLV.1 GNDLVF.1 J6.1 R11.1 R24.1 R25.1 R31.1 R32.1 U5.8(GND) U5.9(PAD) U6.8(GND) U6.9(PAD)
ISO_15V_H: C7.1 C8.1 D4.1(K) ISO15VH.1 L4.2 R4.2
ISO_15V_L: C31.1 C32.1 D9.1(K) ISO15VL.1 L5.2 R26.2
ISO_15V_H_B: C22.1 C24.1 C58.1 D2.1(K) L4.3 R4.1
ISO_15V_L_B: C33.1 C34.1 C59.1 D7.1(K) L5.3 R26.1
ISO_RET_H_B: C22.2 C24.2 L4.4 R13.1 T1.5 T1.6
ISO_RET_L_B: C33.2 C34.2 L5.4 R28.1 T2.5 T2.6
SW: C7.2 C8.2 D4.2(A) ISO15VSW.1 L4.1 R13.2
NetC4_2: C4.2(-) R11.2
NetC30_1: C30.1 U5.5(SS/BIAS)
NetC37_1: C37.1 U6.5(SS/BIAS)
NetC58_2: C58.2 R42.2
NetC59_2: C59.2 R43.2
NetD2_2: D2.2(A) R42.1 T1.7 T1.8
NetD3_1: D3.1(K) D5.1(K)
NetD5_2: D5.2(A) R22.2 T1.4 U5.1(SW)
NetD7_2: D7.2(A) R43.1 T2.7 T2.8
NetD8_1: D8.1(K) D10.1(K)
NetD10_2: D10.2(A) R29.2 T2.4 U6.1(SW)
NetR9_1: R9.1 R24.2 U5.4(EN/UVLO)
NetR22_1: R22.1 U5.2(FB)
NetR23_1: R23.1 R25.2 U5.7(RSET)
NetR23_2: R23.2 U5.6(TC)
NetR27_1: R27.1 R31.2 U6.4(EN/UVLO)
NetR29_1: R29.1 U6.2(FB)
NetR30_1: R30.1 R32.2 U6.7(RSET)
NetR30_2: R30.2 U6.6(TC)

Not connected (* = marked no-connect by the designer): T1 2(NC) 3(NC); T2 2(NC) 3(NC)

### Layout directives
net class VSWNET: ISO_15V_H, ISO_15V_H_B, ISO_RET_H_B, SW
net class PGND: GND_HV, ISO_15V_L, ISO_15V_L_B, ISO_RET_L_B

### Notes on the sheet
- Transformer Specifications
- - Np : Ns = 1 : 1
- - Lpri = 27 uH
- - Lpri,sat > 500 mA
- - Lpri,rms = 100 mA
- - Isolation Strength = 2.5 kVrms
- - Automotive Qualified
- 15 Vin, fixed
- (near R4) DNP
- (near ISO15VH) 15 Vout @ 0.1 A max.
- (near R8) DNP
- (near R13) DNP
- (near R26) DNP
- (near ISO15VL) 15 Vout @ 0.1 A max.
- (near R28) DNP

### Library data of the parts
15VIN = CMP-0055142-2: Test Point, Compact, Red, TH; Manufacturer: Keystone Electronics; CNHeader: FALSE; Green_Lifecycle: Active; Green_REACh: Passed; ContactFinish: Silver; CT: TRUE
15VINF ISO15VH ISO15VL = CMP-0055142-1: as HVIN on sheet PMP31182_LM25180_PWM
C4 = CMP-0750159-1: CAP, AL, 47 µF, 25 V, +/- 20%, 0.05 ohm, AEC-Q200 Grade 1, SMD; Manufacturer: Chemi-Con; TaMin_C: -55°C; Cap_Case: 6.3x5.8mm; CompType: Capacitor; TaMax_C: 125°C; U/M: EA; Value: 47uF; AEC Grade: 1; AEC Category: Q200; AEC Qualified: Y; ESR_ohm: 0.05
C7 C8 C31 C32 = CMP-0091069-1: Cap Ceramic 10uF 25V X7S 10% Pad SMD 0805 +125°C Automotive T/R; Manufacturer: TDK Corporation; AEC Qualified: Yes; AEC Grade: Grade 1; Value: 10µF; Tolerance_%: 0.1%; SizeZ_mm: 1.45mm; TempCo: 22%
C22 C29 C33 C36 = CMP-0079911-1: as C47 on sheet PMP31182_LM25180_PWM
C24 C34 = CMP-0080552-1: CAP, CERM, 22 µF, 25 V,+/- 10%, X7R, AEC-Q200 Grade 1, 1210; Manufacturer: Taiyo Yuden; TaMin_C: -55°C; Polarized: N; SizeAreaWB_mm2: 14.7; U/M: EA; Value: 22uF; TaMax_C: 125°C; SizeZ_mm: 2.7; SizeX_mm: 3.2; SizeY_mm: 2.5; Cap_Case: 1210; SizeArea_mm2: 8; AEC Qualified: Y; AEC Grade: 1; AEC Category: Q200
C25 = CMP-0081062-1: CAP, CERM, 10 µF, 25 V,+/- 5%, X7R, AEC-Q200 Grade 1, 1206; Manufacturer: Kemet; TaMin_C: -55°C; Polarized: N; SizeAreaWB_mm2: 10.92; U/M: EA; Value: 10uF; TaMax_C: 125°C; SizeZ_mm: 1.8; SizeX_mm: 3.2; SizeY_mm: 1.6; SizeArea_mm2: 5.12; AEC Qualified: Y; AEC Grade: 1; AEC Category: Q200
C28 C35 = CMP-0009163-2: CAP, CERM, 4.7 uF, 50 V, +/- 20%, X7R, AEC-Q200 Grade 1, 1210; Manufacturer: TDK; TaMin_C: -55°C; Polarized: N; SizeAreaWB_mm2: 14.7; Value1: Unknown; U/M: EA; Value: 4.7uF; TaMax_C: 125°C; SizeZ_mm: 2.8; SizeX_mm: 3.2; SizeY_mm: 2.5; Cap_Case: 1210; SizeArea_mm2: 8; AEC Qualified: Y; Cap_F: 4.7µF; AEC Grade: 1; AEC Category: Q200
C30 C37 = CMP-0006757-5: CAP, CERM, 0.047 uF, 25 V, +/- 5%, X7R, 0603; Manufacturer: AVX; TaMin_C: -55°C; ESR_ohm: 0.052; Polarized: N; SizeAreaWB_mm2: 4.68; Value1: 0.052 ohm; U/M: EA; TaMax_C: 125°C; SizeZ_mm: 1; SizeX_mm: 1.6; SizeY_mm: 0.8; SizeArea_mm2: 1.28; AEC Category: Q200
C58 C59 = CMP-0007196-4: CAP, CERM, 22 pF, 50 V, +/- 5%, C0G/NP0, 0603; Manufacturer: MuRata; TaMin_C: -55°C; Polarized: N; SizeAreaWB_mm2: 4.68; Value1: Unknown; U/M: EA; Value: 22pF; TaMax_C: 125°C; SizeZ_mm: 1; SizeX_mm: 1.6; SizeY_mm: 0.8; SizeArea_mm2: 1.28; AEC Category: Q200
D2 D7 = CMP-0028850-2: Diode, Schottky, 40 V, 2 A, AEC-Q101, PowerDI123; PartNumber: DFLS240-7; Manufacturer: Diodes Inc.; SizeArea_mm2: 6.586; Value: 40V; Green_REACh: Incomplete; Value2: 0.5V; Green_Lifecycle: Not Set; SizeX_mm: 3.7; AEC Qualified: Y; SizeY_mm: 1.78; AEC Category: Q101; Io_A: 2A; TJmax_C: 125°C; SizeAreaWB_mm2: 13.066; SizeZ_mm: 0.98; Vf_V: 500mV
D3 D8 = CMP-0005415-3: Diode, Zener, 24 V, 1 W, PowerDI123; Manufacturer: Diodes Inc.; PartNumber: DFLZ24-7; SizeX_mm: 3.7; SizeY_mm: 1.78; Value1: 1W; SizeAreaWB_mm2: 13.066; AEC Category: Q101; SizeArea_mm2: 6.586; RJA_CperW: 110; SizeZ_mm: 0.98
D4 D9 = CMP-0084402-3: Diode, Zener, 18 V, 500 mW, AEC-Q101, SOD-123; Manufacturer: Diodes Inc.; SizeX_mm: 3.85; SizeAreaWB_mm2: 13.095; Green_REACh: Incomplete; AEC Category: Q101; AEC Qualified: Y; Value1: 0.5W; SizeY_mm: 1.7; Power_W: 500mW; SizeZ_mm: 1.35; RJA_CperW: 338; SizeArea_mm2: 6.545; Green_Lifecycle: Active
D5 D10 = CMP-0029006-2: Diode, Ultrafast, 100 V, 0.25 A, SOD-323; PartNumber: BAS316,115; Manufacturer: Nexperia; SizeY_mm: 1.35; Value1: 0.25A; SizeAreaWB_mm2: 8.695; SizeZ_mm: 1; Io_A: 250mA; Value2: 1.4V; SizeX_mm: 2.7; Green_REACh: Incomplete; TJmax_C: 150°C; Green_Lifecycle: Not Set; Vr_V: 100V; AEC Category: Q101; Value: 100V; SizeArea_mm2: 3.645
GNDLV GNDLVF ISO15VGND ISO15VSW = CMP-0055143-1: as GND_LV on sheet PMP31182_LM25180_PWM
J6 = CMP-0054974-1: Terminal Block, 2x1, 2.54mm, TH; Manufacturer: TE Connectivity; CNHeader: FALSE; Green_Lifecycle: Active; Green_REACh: Passed; CT: TRUE
L3 = CMP-0060122-1: Inductor, Wirewound, Ferrite, 240 nH, 0.85 A, 0.119999 ohm, SMD; Manufacturer: Coilcraft; PartNumber: 0603AF-241KRB; Irms: 0.85A @ 15C rise; Green_Lifecycle: Not Set; SizeAreaWB_mm2: 5.936; DCR_ohm: 1.19999d; Green_REACh: Incomplete; Value: 240nH; Imax_A: 8.5dA; SizeZ_mm: 0.91; SizeX_mm: 1.8; SizeY_mm: 1.12; Value2: 0.85A; SizeArea_mm2: 2.016; AEC Category: Q200
L4 L5 = CMP-0090488-1: 2 Line Common Mode Choke Surface Mount 90 Ohms @ 100MHz 400mA DCR 190mOhm; Manufacturer: TDK; SizeZ_mm: 1.3mm; DCR_ohm: 0.19; AEC Qualified: Yes; AEC Grade: Grade 2; Impedance At Frequency: 90Ω @ 100MHz
R4 R8 R13 R26 R28 = CMP-0089143-1: as R18 on sheet PMP31182_LM25180_GaN
R9 R23 R27 R30 = CMP-0024094-3: RES, 309 k, 0.1%, 0.1 W, 0603; Manufacturer: Yageo America; Power_W: 100mW; TempCo: 25 ppm/C; U/M: EA; Value: 309k; EIA_Code: E192; SizeX_mm: 1.6; SizeY_mm: 0.8; SizeZ_mm: 1; Value2: 0.1W; SizeArea_mm2: 1.28; VDC_V: 75V; AEC Category: Q200
R11 = CMP-0022714-3: RES, 0.33, 1%, 0.1 W, AEC-Q200 Grade 0, 0603; Manufacturer: Panasonic; Power_W: 100mW; TempCo: 300 ppm/C; Value_Code: R330; Value: 0.33; EIA_Code: E96; SizeX_mm: 1.6; SizeY_mm: 0.8; SizeZ_mm: 1; Value2: 0.1W; SizeArea_mm2: 1.28; AEC Qualified: Y; AEC Category: Q200; AEC Grade: 0; SizeAreaWB_mm2: 4.68
R22 R29 = CMP-0024703-3: RES, 154 k, 0.5%, 0.1 W, 0603; Manufacturer: Yageo America; Power_W: 100mW; TempCo: 50 ppm/C; U/M: EA; Value: 154k; EIA_Code: E192; SizeX_mm: 1.6; SizeY_mm: 0.8; SizeZ_mm: 1; Value2: 0.1W; SizeArea_mm2: 1.28; VDC_V: 75V; AEC Category: Q200
R24 R31 = CMP-0024164-3: RES, 37.4 k, 0.1%, 0.1 W, 0603; Manufacturer: Yageo America; Power_W: 100mW; TempCo: 25 ppm/C; Value_Code: 37k4; U/M: EA; Value: 37.4k; EIA_Code: E192; SizeX_mm: 1.6; SizeY_mm: 0.8; SizeZ_mm: 1; Value2: 0.1W; SizeArea_mm2: 1.28; VDC_V: 75V; AEC Category: Q200
R25 R32 = CMP-0023704-3: RES, 12.1 k, 0.1%, 0.1 W, 0603; Manufacturer: Yageo America; Power_W: 100mW; TempCo: 25 ppm/C; Value_Code: 12k1; U/M: EA; Value: 12.1k; EIA_Code: E192; SizeX_mm: 1.6; SizeY_mm: 0.8; SizeZ_mm: 1; Value2: 0.1W; SizeArea_mm2: 1.28; VDC_V: 75V; AEC Category: Q200
R42 R43 = CMP-0022736-4: RES, 100, 1%, 0.1 W, 0603; Manufacturer: Yageo; Power_W: 100mW; TempCo: 100 ppm/C; Value_Code: 100R; Value: 100; EIA_Code: E96; SizeX_mm: 1.6; SizeY_mm: 0.8; SizeZ_mm: 1; Value2: 0.1W; SizeArea_mm2: 1.28; AEC Qualified: N; VDC_V: 75V; AEC Category: Q200; SizeAreaWB_mm2: 4.68
T1 T2 = CMP-11284-000033-1: No-Opto Flyback Transformer, 1:1, 0.168:0.168Ohm, 2500Vrms, 9.3x10.2x10.6mm
U5 U6 = CMP-0750186-1: LM25180-Q1 42-VIN PSR Flyback DC/DC Converter With 65-V, 1.5-A Integrated MOSFET, NGU0008C (WSON-8); Manufacturer: Texas Instruments; Alternate PartNumber: LM25180QNGUTQ1; SizeArea_mm2: 16; SizeY_mm: 4; SizeAreaWB_mm2: 25; AEC Qualified: Y; SizeZ_mm: 0.8; CompType: IC; AEC Category: Q200

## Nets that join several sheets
5V: PMP31182_LM25180_GaN (6 pins), PMP31182_LM25180_PWM (17 pins)
15V_F: PMP31182_LM25180_PWM (J7.1), PMP31182_LM25180_power_supply (16 pins)
GND_HV: PMP31182_LM25180_GaN (42 pins), PMP31182_LM25180_PWM (C49.2 GNDHV.1 J5.1), PMP31182_LM25180_power_supply (6 pins)
GND_LV: PMP31182_LM25180_GaN (12 pins), PMP31182_LM25180_PWM (23 pins), PMP31182_LM25180_power_supply (19 pins)
HVBUS: PMP31182_LM25180_GaN (24 pins), PMP31182_LM25180_PWM (C49.1 HVIN.1 J5.2)
ISO_15V_H: PMP31182_LM25180_GaN (R1.1), PMP31182_LM25180_power_supply (6 pins)
ISO_15V_L: PMP31182_LM25180_GaN (R3.1), PMP31182_LM25180_power_supply (6 pins)
Bot_FET_FAULT: PMP31182_LM25180_GaN (C57.1 R40.2), PMP31182_LM25180_PWM (C52.1 R14.1 U8.5)
Bot_FET_OC: PMP31182_LM25180_GaN (C56.1 R39.2), PMP31182_LM25180_PWM (C55.1 R17.1 U8.6)
Bot_FET_PWM: PMP31182_LM25180_GaN (R16.1), PMP31182_LM25180_PWM (R38.2)
SW: PMP31182_LM25180_GaN (50 pins), PMP31182_LM25180_power_supply (6 pins)
Top_FET_FAULT: PMP31182_LM25180_GaN (C40.1 R19.2), PMP31182_LM25180_PWM (C50.1 R10.1 U9.1)
Top_FET_OC: PMP31182_LM25180_GaN (C39.1 R20.2), PMP31182_LM25180_PWM (C51.1 R12.1 U9.2)
Top_FET_PWM: PMP31182_LM25180_GaN (R7.1), PMP31182_LM25180_PWM (R34.2 Top_FET_PWM.1)

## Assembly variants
001: all parts fitted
